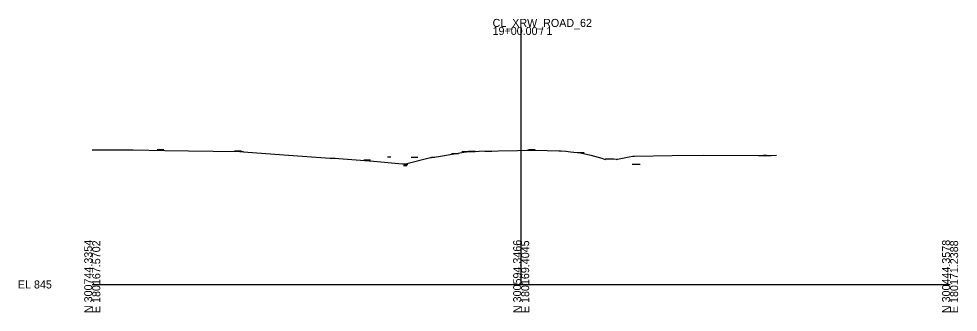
# Model space of a CAD drawing. Extents: x -26 to 303, y 490 to 4093.
# Drawn here: x -25.7 to 302.8, y 3990.3 to 4092.8 of the extents above; entities that cross this region are included whole.
import ezdxf

# ---------------------------------------------------------------- set-up
doc = ezdxf.new("R2010")
doc.units = 0
for name, color, linetype in [('Default', 7, 'Continuous'), ('DR_X_Text', 7, 'Continuous'), ('GK_Cells', 7, 'Continuous'), ('SV_X_Text_Comment', 7, 'Continuous'), ('SV_X_Text_Description', 7, 'Continuous'), ('SV_X_Text_Elevation', 7, 'Continuous'), ('SV_X_Text_Name', 7, 'Continuous'), ('XS_X_Ground_Line', 7, 'Continuous')]:
    doc.layers.add(name, color=color, linetype=linetype)

msp = doc.modelspace()

# ---------------------------------------------------------------- linework, layer by layer
at = {"layer": 'DR_X_Text'}
msp.add_lwpolyline([(191.63, 4041.9), (188.83, 4041.9)], dxfattribs=at)
msp.add_lwpolyline([(191.63, 4041.9), (188.83, 4041.9)], dxfattribs=at)
at = {"layer": 'GK_Cells'}
for p, q in [((150, 4000), (150, 4090)), ((0, 4000), (150, 4000)), ((150, 4000), (300, 4000))]:
    msp.add_line(p, q, dxfattribs=at)
at = {"layer": 'SV_X_Text_Comment'}
for points in [[(52.85, 4046.39), (51.65, 4046.39)], [(119.8, 4044.32), (118.59, 4044.32)], [(128.04, 4045.7), (126.84, 4045.7)], [(139.74, 4046.43), (138.54, 4046.43)], [(235.83, 4045.1), (234.63, 4045.1)], [(84.92, 4044.07), (83.72, 4044.07)], [(110.32, 4041.86), (109.12, 4041.86)]]:
    msp.add_lwpolyline(points, dxfattribs=at)
at = {"layer": 'SV_X_Text_Description'}
for points in [[(126.84, 4045.7), (125.64, 4045.7)], [(138.54, 4046.43), (137.34, 4046.43)], [(110.06, 4041.41), (108.86, 4041.41)]]:
    msp.add_lwpolyline(points, dxfattribs=at)
at = {"layer": 'SV_X_Text_Elevation'}
for points in [[(25.09, 4047.05), (23.89, 4047.05)], [(52.16, 4046.63), (50.96, 4046.63)], [(104.47, 4044.52), (103.27, 4044.52)], [(113.88, 4044.42), (112.68, 4044.42)], [(131.66, 4046.38), (130.46, 4046.38)], [(133.96, 4046.51), (132.76, 4046.51)], [(154.91, 4047.01), (153.71, 4047.01)], [(172.08, 4046.02), (170.88, 4046.02)], [(97.32, 4043.49), (96.12, 4043.49)]]:
    msp.add_lwpolyline(points, dxfattribs=at)
at = {"layer": 'SV_X_Text_Name'}
for points in [[(23.89, 4047.05), (22.69, 4047.05)], [(50.96, 4046.63), (49.76, 4046.63)], [(112.68, 4044.42), (111.48, 4044.42)], [(130.46, 4046.38), (129.26, 4046.38)], [(132.76, 4046.51), (131.56, 4046.51)], [(153.71, 4047.01), (152.51, 4047.01)], [(170.88, 4046.02), (169.68, 4046.02)], [(96.12, 4043.49), (94.92, 4043.49)]]:
    msp.add_lwpolyline(points, dxfattribs=at)
at = {"layer": 'XS_X_Ground_Line'}
msp.add_lwpolyline([(0, 4047.06), (13.02, 4047.02), (13.65, 4047.02), (14.25, 4047.02), (25.33, 4046.85), (33.62, 4046.75), (42.28, 4046.6), (51.56, 4046.42), (52.08, 4046.41), (52.92, 4046.39), (66.94, 4045.32), (83.19, 4044.17), (83.95, 4044.12), (84.66, 4044.09), (98.37, 4043.08), (108.55, 4042.12), (109.6, 4042.21), (118.29, 4044.33), (118.64, 4044.37), (121.09, 4044.76), (130.6, 4046.35), (130.88, 4046.37), (133.23, 4046.49), (133.45, 4046.49), (133.89, 4046.49), (135.28, 4046.55), (148.68, 4046.82), (151.95, 4046.9), (153.79, 4046.96), (154.99, 4046.92), (163.21, 4046.66), (164.01, 4046.67), (165.62, 4046.61), (167.27, 4046.35), (170.72, 4045.96), (174.38, 4045.16), (178.19, 4044.12), (179.33, 4043.67), (179.56, 4043.86), (182.37, 4043.89), (183.22, 4043.84), (183.46, 4043.7), (183.69, 4043.84), (187.74, 4044.58), (189.08, 4044.82), (189.68, 4044.82), (202.82, 4045.03), (213.67, 4045.17), (232.97, 4045.1), (233.8, 4045.08), (235.25, 4045.1), (235.87, 4045.09), (236.6, 4045.11), (237.4, 4045.12), (239.33, 4045.15)], dxfattribs=at)

# ---------------------------------------------------------------- texts
at = {"layer": 'Default'}
msp.add_text('-', height=0.0001, dxfattribs=at).set_placement((0, 4000))
at = {"layer": 'GK_Cells'}
for s, p in [('CL_XRW_ROAD_62', (140, 4090)), ('19+00.00 / 1', (140, 4087.2)), ('EL 845', (-26, 3998.6))]:
    msp.add_text(s, height=2.8, dxfattribs=at).set_placement(p)
for s, p in [('N 300744.3354', (0, 3990)), ('E 180167.5702', (2.8, 3990)), ('N 300594.3466', (150, 3990)), ('E 180169.4045', (152.8, 3990)), ('N 300444.3578', (300, 3990)), ('E 180171.2388', (302.8, 3990))]:
    msp.add_text(s, height=2.8, rotation=90, dxfattribs=at).set_placement(p)

doc.saveas('drawing.dxf')
